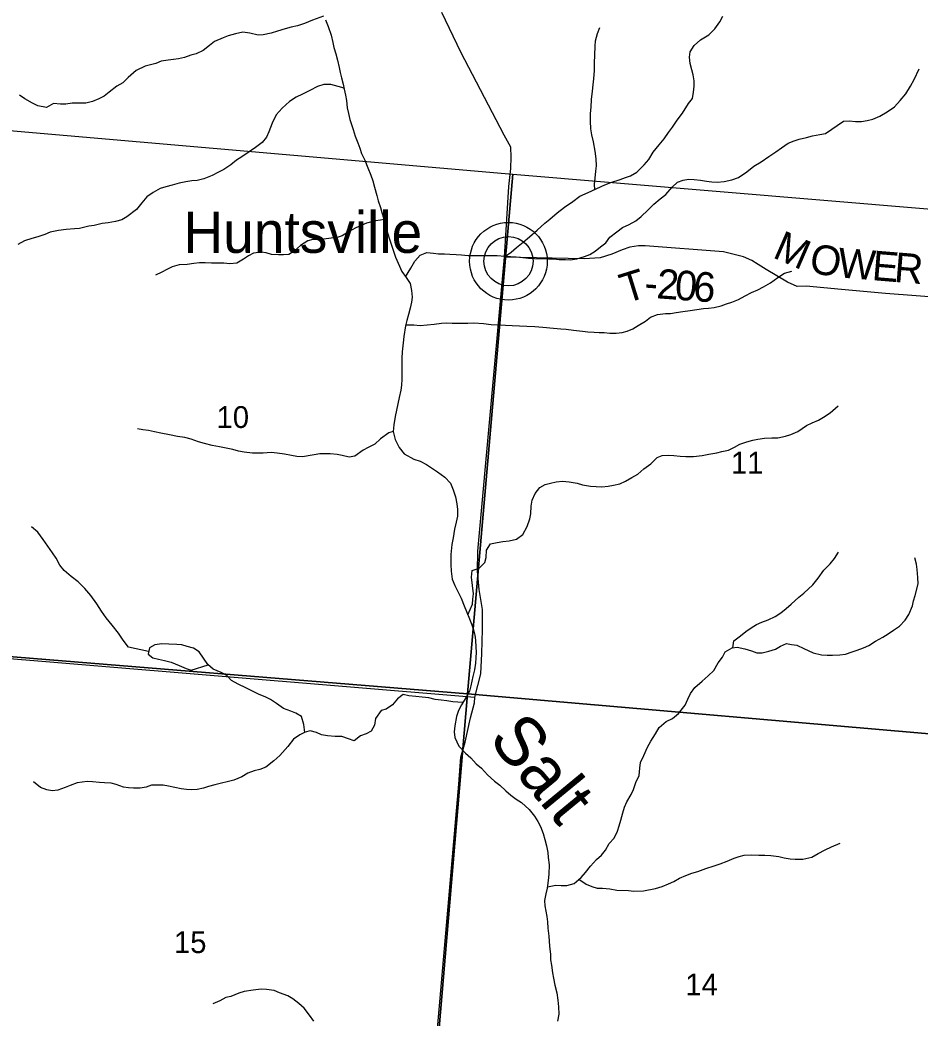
# Model space of a CAD drawing. Extents: x 1643459 to 2064572, y 425441 to 780708.
# Drawn here: x 1887412 to 1896522, y 553249 to 563347 of the extents above; entities that cross this region are included whole.
import ezdxf

# ---------------------------------------------------------------- set-up
doc = ezdxf.new("R2010")
doc.units = 0
for name, color, linetype in [('GE_P_Alignment_100_Curve_Data', 7, 'Continuous'), ('GM_X_Adjacent_County', 7, 'Continuous'), ('GM_X_Major_River', 7, 'Continuous'), ('GM_X_Major_River_Text', 7, 'Continuous'), ('GM_X_Minor_Lake', 7, 'Continuous'), ('GM_X_Rail_Line', 7, 'Continuous'), ('GM_X_State_Route', 7, 'Continuous'), ('GM_X_State_Shield', 7, 'Continuous'), ('GM_X_Township_ROW', 7, 'Continuous'), ('GM_X_Unincorporated_Text', 7, 'Continuous'), ('GM_X_US_Route', 7, 'Continuous')]:
    doc.layers.add(name, color=color, linetype=linetype)

msp = doc.modelspace()

# ---------------------------------------------------------------- linework, layer by layer
at = {"layer": 'GE_P_Alignment_100_Curve_Data'}
for radius in [393, 249]:
    msp.add_circle((1892356, 560906), radius, dxfattribs=at)
at = {"layer": 'GM_X_Major_River_Text'}
for points in [[(1894885, 560872), (1894819, 560915), (1894736, 560952), (1894532, 561003), (1893739, 561062), (1893673, 561061), (1893585, 561050), (1893508, 561021), (1893404, 560978), (1893283, 560939), (1893123, 560929), (1892315, 560949)], [(1897503, 560477), (1896172, 560579), (1895728, 560619), (1895368, 560653), (1895278, 560652), (1895179, 560696), (1894966, 560821), (1894885, 560872)], [(1876241, 557816), (1881411, 557404), (1886775, 556930), (1892015, 556496)]]:
    msp.add_lwpolyline(points, dxfattribs=at)
at = {"layer": 'GM_X_Minor_Lake'}
msp.add_lwpolyline([(1891467, 551170), (1891853, 555616), (1891875, 555889), (1891917, 556041), (1891972, 556288), (1892012, 556438), (1892015, 556496), (1892078, 556732), (1892086, 556937), (1892095, 557179), (1892092, 557384), (1892058, 557585), (1892043, 557770), (1892047, 557973), (1892315, 560949), (1892360, 561661), (1892381, 561844), (1892382, 561960), (1892381, 562062), (1892313, 562182), (1891875, 563022), (1891682, 563424)], dxfattribs=at)
at = {"layer": 'GM_X_Rail_Line'}
msp.add_line((1892356, 560906), (1892356, 560906), dxfattribs=at)
at = {"layer": 'GM_X_State_Route'}
for points in [[(1892399, 561787), (1891943, 556530), (1886800, 556947), (1887147, 562241)], [(1897606, 561351), (1897162, 556078), (1891943, 556530), (1892399, 561787)], [(1886800, 556947), (1891943, 556530), (1891491, 551199), (1886336, 551627)], [(1891943, 556530), (1897162, 556078), (1896690, 550827), (1891491, 551199)]]:
    msp.add_lwpolyline(points, close=True, dxfattribs=at)
at = {"layer": 'GM_X_Unincorporated_Text'}
for points in [[(1890503, 563347), (1890533, 563281), (1890562, 563193), (1890580, 563120), (1890590, 563070), (1890608, 563004), (1890626, 562941), (1890642, 562865), (1890654, 562815), (1890668, 562761), (1890682, 562698), (1890694, 562646), (1890708, 562586), (1890716, 562532), (1890724, 562457), (1890736, 562401), (1890752, 562341), (1890784, 562240), (1890804, 562172), (1890832, 562103), (1890852, 562051), (1890868, 561995), (1890902, 561928), (1890934, 561850), (1890962, 561778), (1890983, 561719), (1890999, 561657), (1891023, 561570), (1891039, 561516), (1891061, 561450), (1891075, 561398), (1891093, 561345), (1891113, 561271), (1891131, 561195), (1891157, 561118), (1891213, 560949), (1891239, 560887), (1891277, 560802)], [(1891277, 560802), (1891320, 560742), (1891360, 560681), (1891376, 560611), (1891382, 560541), (1891376, 560491), (1891361, 560433), (1891345, 560367), (1891327, 560307), (1891315, 560253), (1891298, 560144), (1891290, 560080), (1891280, 559990), (1891278, 559926), (1891277, 559713), (1891273, 559651), (1891267, 559601), (1891250, 559529), (1891224, 559399), (1891210, 559335), (1891197, 559252), (1891189, 559182), (1891211, 559102), (1891249, 559023), (1891300, 558959), (1891397, 558902), (1891463, 558883), (1891528, 558851), (1891586, 558810), (1891639, 558774), (1891713, 558721), (1891770, 558661), (1891798, 558594), (1891820, 558522), (1891832, 558452), (1891842, 558395), (1891840, 558327), (1891827, 558267), (1891809, 558197), (1891795, 558107), (1891782, 558039), (1891772, 557940), (1891774, 557838), (1891776, 557772), (1891786, 557688), (1891814, 557627), (1891848, 557559), (1891876, 557496), (1891908, 557420), (1891930, 557362), (1891961, 557289), (1891985, 557227), (1892001, 557177), (1892017, 557122), (1892023, 557072), (1892027, 557002), (1892029, 556952), (1892026, 556892), (1892022, 556841), (1892012, 556773), (1891996, 556703), (1891975, 556609), (1891963, 556555), (1891929, 556497), (1891882, 556419), (1891852, 556359), (1891831, 556299), (1891813, 556205), (1891807, 556145), (1891815, 556089), (1891853, 556000), (1891921, 555928), (1891974, 555881), (1892028, 555820), (1892083, 555776), (1892145, 555711), (1892214, 555647), (1892270, 555604), (1892328, 555548), (1892379, 555505), (1892433, 555464), (1892488, 555430), (1892566, 555359), (1892619, 555293), (1892653, 555238), (1892681, 555186), (1892709, 555117), (1892725, 555057), (1892741, 554991), (1892755, 554923), (1892759, 554872), (1892769, 554800), (1892765, 554706), (1892759, 554640), (1892748, 554564), (1892736, 554506), (1892722, 554439), (1892724, 554383), (1892744, 554275), (1892750, 554221), (1892756, 554160)], [(1892756, 554160), (1892764, 554078), (1892767, 554026), (1892773, 553976), (1892781, 553893), (1892783, 553839), (1892791, 553783), (1892803, 553705), (1892813, 553652), (1892827, 553582), (1892845, 553504), (1892857, 553430), (1892863, 553361), (1892865, 553289), (1892851, 553219)]]:
    msp.add_lwpolyline(points, dxfattribs=at)
at = {"layer": 'GM_X_US_Route'}
for points in [[(1892323, 560959), (1892326, 560959), (1892385, 560999), (1892437, 561045), (1892504, 561100), (1892569, 561154), (1892648, 561222), (1892725, 561293), (1892775, 561333), (1892850, 561395), (1892923, 561452), (1893006, 561512), (1893077, 561564), (1893131, 561587), (1893200, 561617), (1893251, 561641), (1893333, 561680), (1893392, 561704), (1893487, 561733), (1893540, 561753), (1893590, 561770), (1893657, 561808), (1893728, 561882), (1893778, 561934), (1893821, 562009), (1893880, 562083), (1893932, 562145), (1893975, 562209), (1894015, 562263), (1894062, 562333), (1894117, 562406), (1894179, 562502), (1894218, 562554), (1894230, 562616), (1894236, 562678), (1894234, 562731), (1894225, 562793), (1894213, 562843), (1894196, 562907), (1894187, 562972), (1894195, 563026), (1894237, 563088), (1894300, 563145), (1894385, 563197), (1894446, 563259), (1894496, 563330), (1894525, 563386)], [(1890484, 563385), (1890374, 563344), (1890293, 563313), (1890220, 563287), (1890158, 563274), (1890095, 563256), (1890020, 563233), (1889956, 563213), (1889875, 563196), (1889822, 563192), (1889738, 563213), (1889669, 563223), (1889592, 563208), (1889521, 563186), (1889469, 563168), (1889382, 563131), (1889329, 563089), (1889265, 563040), (1889196, 563006), (1889141, 562990), (1889077, 562969), (1889018, 562955), (1888967, 562947), (1888913, 562940), (1888842, 562930), (1888786, 562907), (1888678, 562881), (1888587, 562836), (1888507, 562764), (1888452, 562712), (1888391, 562677), (1888316, 562617), (1888264, 562575), (1888209, 562550), (1888146, 562522), (1888078, 562505), (1888011, 562505), (1887942, 562504), (1887876, 562496), (1887823, 562496), (1887751, 562501), (1887682, 562461), (1887593, 562480), (1887538, 562506), (1887460, 562551), (1887409, 562588)], [(1893229, 561630), (1893228, 561685), (1893235, 561745), (1893241, 561819), (1893247, 561873), (1893245, 561943), (1893235, 562020), (1893217, 562114), (1893199, 562186), (1893189, 562245), (1893185, 562325), (1893188, 562401), (1893192, 562465), (1893198, 562544), (1893206, 562626), (1893214, 562690), (1893221, 562752), (1893227, 562836), (1893227, 562912), (1893229, 562991), (1893233, 563083), (1893238, 563135), (1893256, 563211), (1893280, 563271)], [(1895566, 562197), (1895748, 562322), (1895803, 562328), (1895870, 562321), (1895928, 562321), (1895985, 562329), (1896043, 562344), (1896114, 562374), (1896189, 562419), (1896262, 562469), (1896320, 562533), (1896379, 562601), (1896424, 562679), (1896462, 562746), (1896513, 562854)], [(1890693, 562649), (1890692, 562658), (1890631, 562673), (1890558, 562695), (1890488, 562694), (1890423, 562674), (1890346, 562634), (1890273, 562597), (1890209, 562565), (1890140, 562522), (1890067, 562456), (1890006, 562388), (1889964, 562304), (1889931, 562216), (1889907, 562160), (1889862, 562106), (1889796, 562057), (1889731, 562013), (1889656, 561964), (1889603, 561930), (1889545, 561882), (1889476, 561836), (1889423, 561807), (1889357, 561775), (1889272, 561740), (1889207, 561722), (1889153, 561718), (1889092, 561711), (1889025, 561695), (1888951, 561676), (1888890, 561660), (1888831, 561641), (1888759, 561601), (1888696, 561557), (1888645, 561496), (1888593, 561430), (1888495, 561354), (1888443, 561326), (1888378, 561307), (1888305, 561295), (1888245, 561288), (1888162, 561268), (1888109, 561261), (1888014, 561239), (1887964, 561234), (1887879, 561226), (1887802, 561217), (1887719, 561199), (1887663, 561178), (1887594, 561154), (1887532, 561135), (1887457, 561111), (1887390, 561075)], [(1891314, 560750), (1891368, 560836), (1891407, 560906), (1891462, 560966), (1891530, 560993), (1891599, 560987), (1891649, 560980), (1891710, 560980), (1891763, 560977), (1891827, 560975), (1891880, 560971), (1891948, 560964), (1892055, 560963), (1892118, 560963), (1892175, 560964), (1892243, 560964), (1892318, 560959), (1892377, 560955), (1892433, 560950), (1892500, 560944), (1892560, 560937), (1892619, 560933), (1892762, 560932), (1892815, 560930), (1892869, 560925), (1892932, 560923), (1892982, 560922), (1893049, 560932), (1893126, 560953), (1893180, 560975), (1893233, 561009), (1893286, 561053), (1893342, 561094), (1893381, 561150), (1893452, 561204), (1893510, 561249), (1893579, 561279), (1893644, 561315), (1893700, 561360), (1893767, 561424), (1893828, 561484), (1893893, 561536), (1893949, 561581), (1894014, 561657), (1894067, 561705), (1894125, 561726), (1894178, 561736), (1894234, 561734), (1894299, 561725), (1894362, 561715), (1894414, 561708), (1894469, 561706), (1894539, 561713), (1894616, 561731), (1894685, 561752), (1894770, 561812), (1894841, 561868), (1894915, 561913), (1894992, 561967), (1895063, 562014), (1895120, 562052), (1895188, 562102), (1895249, 562125), (1895300, 562141), (1895372, 562159), (1895435, 562174), (1895506, 562190), (1895566, 562197)], [(1891097, 561330), (1891062, 561323), (1891010, 561316), (1890921, 561290), (1890864, 561269), (1890812, 561243), (1890737, 561203), (1890674, 561164), (1890624, 561148), (1890563, 561139), (1890488, 561129), (1890438, 561125), (1890377, 561126), (1890327, 561114), (1890252, 561067), (1890191, 561013), (1890135, 560975), (1890080, 560970), (1890030, 560972), (1889959, 560976), (1889904, 560991), (1889854, 560999), (1889775, 560988), (1889725, 560960), (1889674, 560928), (1889607, 560885), (1889535, 560879), (1889474, 560886), (1889407, 560888), (1889351, 560885), (1889286, 560891), (1889228, 560890), (1889173, 560882), (1889104, 560874), (1889024, 560869), (1888951, 560849), (1888900, 560822), (1888848, 560796), (1888785, 560766)], [(1891317, 560264), (1891397, 560264), (1891462, 560257), (1891533, 560263), (1891603, 560270), (1891680, 560280), (1891731, 560282), (1891785, 560281), (1891860, 560279), (1891945, 560280), (1892007, 560282), (1892104, 560277), (1892181, 560266), (1892258, 560262), (1892325, 560259), (1892395, 560257), (1892468, 560252), (1892541, 560250), (1892623, 560245), (1892704, 560238), (1892811, 560230), (1892886, 560223), (1892940, 560219), (1893013, 560208), (1893106, 560197), (1893161, 560193), (1893223, 560188), (1893274, 560186), (1893326, 560184), (1893383, 560179), (1893445, 560179), (1893506, 560184), (1893558, 560198), (1893615, 560222), (1893670, 560255), (1893742, 560301), (1893795, 560341), (1893864, 560366), (1893947, 560376), (1893997, 560379), (1894052, 560387), (1894122, 560397), (1894195, 560408), (1894264, 560418), (1894330, 560427), (1894381, 560431), (1894438, 560438), (1894510, 560454), (1894563, 560474), (1894617, 560491), (1894686, 560519), (1894751, 560556), (1894816, 560590), (1894880, 560618), (1894939, 560647), (1895008, 560689), (1895081, 560741), (1895149, 560786), (1895224, 560806)], [(1891945, 557327), (1891993, 557435), (1891997, 557486), (1892002, 557542), (1891992, 557624), (1891982, 557708), (1891990, 557778), (1892059, 557800), (1892117, 557858), (1892132, 557910), (1892134, 557984), (1892176, 558046), (1892241, 558061), (1892300, 558071), (1892362, 558077), (1892437, 558094), (1892502, 558142), (1892546, 558222), (1892573, 558300), (1892581, 558352), (1892587, 558428), (1892595, 558490), (1892628, 558556), (1892672, 558618), (1892729, 558648), (1892780, 558661), (1892840, 558675), (1892903, 558682), (1892969, 558674), (1893052, 558661), (1893107, 558645), (1893185, 558632), (1893244, 558626), (1893301, 558623), (1893365, 558631), (1893420, 558639), (1893482, 558654), (1893541, 558682), (1893604, 558717), (1893664, 558753), (1893727, 558807), (1893796, 558858), (1893861, 558920), (1893913, 558942), (1893976, 558943), (1894030, 558941), (1894093, 558935), (1894150, 558930), (1894230, 558932), (1894317, 558941), (1894384, 558954), (1894465, 558966), (1894517, 558980), (1894582, 558995), (1894645, 559025), (1894697, 559054), (1894768, 559080), (1894829, 559096), (1894879, 559107), (1894948, 559117), (1895022, 559118), (1895083, 559120), (1895160, 559135), (1895214, 559153), (1895285, 559185), (1895372, 559244), (1895429, 559270), (1895493, 559299), (1895544, 559327), (1895611, 559373), (1895694, 559444)], [(1891189, 559182), (1891147, 559169), (1891062, 559109), (1891003, 559057), (1890936, 559020), (1890886, 558996), (1890803, 558934), (1890744, 558925), (1890672, 558941), (1890621, 558950), (1890552, 558958), (1890447, 558957), (1890391, 558949), (1890328, 558938), (1890276, 558926), (1890213, 558931), (1890161, 558939), (1890088, 558954), (1890015, 558964), (1889955, 558971), (1889872, 558965), (1889815, 558964), (1889765, 558964), (1889682, 558973), (1889625, 558983), (1889567, 559000), (1889500, 559014), (1889430, 559027), (1889359, 559041), (1889280, 559062), (1889220, 559080), (1889145, 559107), (1889080, 559123), (1889008, 559134), (1888927, 559151), (1888838, 559167), (1888773, 559180), (1888713, 559192), (1888654, 559201), (1888602, 559211)], [(1888714, 556958), (1888512, 557003), (1888456, 557072), (1888408, 557143), (1888345, 557225), (1888283, 557298), (1888236, 557364), (1888190, 557441), (1888130, 557524), (1888069, 557594), (1888001, 557661), (1887930, 557716), (1887858, 557776), (1887817, 557831), (1887777, 557903), (1887741, 557956), (1887694, 558022), (1887648, 558091), (1887594, 558165), (1887529, 558218)], [(1894626, 556996), (1894636, 557065), (1894703, 557117), (1894760, 557159), (1894812, 557198), (1894865, 557230), (1894921, 557254), (1894986, 557279), (1895055, 557311), (1895112, 557349), (1895166, 557392), (1895219, 557436), (1895294, 557508), (1895346, 557549), (1895437, 557633), (1895490, 557699), (1895547, 557779), (1895611, 557844), (1895656, 557898), (1895697, 557962)], [(1892750, 554575), (1892837, 554593), (1892888, 554591), (1892948, 554590), (1893021, 554610), (1893092, 554671), (1893135, 554723), (1893185, 554785), (1893246, 554853), (1893297, 554897), (1893337, 554948), (1893376, 555016), (1893426, 555070), (1893461, 555140), (1893477, 555194), (1893493, 555252), (1893514, 555326), (1893530, 555382), (1893554, 555436), (1893597, 555510), (1893621, 555562), (1893644, 555632), (1893678, 555702), (1893686, 555778), (1893692, 555836), (1893725, 555904), (1893765, 555990), (1893798, 556050), (1893843, 556126), (1893883, 556190), (1893952, 556248), (1894015, 556281), (1894077, 556329), (1894144, 556415), (1894170, 556475), (1894197, 556533), (1894243, 556595), (1894318, 556658), (1894377, 556710), (1894436, 556764), (1894478, 556844), (1894521, 556900), (1894549, 556953), (1894620, 556995), (1894670, 557003), (1894747, 556986), (1894816, 556966), (1894870, 556945), (1894923, 556945), (1894992, 556962), (1895058, 556982), (1895111, 557012), (1895171, 557037), (1895222, 557029), (1895274, 557022), (1895345, 556988), (1895440, 556943), (1895523, 556924), (1895581, 556922), (1895636, 556921), (1895710, 556923), (1895767, 556931), (1895834, 556954), (1895884, 556972), (1895949, 556995), (1896002, 557017), (1896072, 557061), (1896145, 557102), (1896198, 557138), (1896254, 557174), (1896313, 557215), (1896370, 557273), (1896408, 557333), (1896445, 557419), (1896457, 557469), (1896471, 557523), (1896502, 557643), (1896500, 557707), (1896492, 557786), (1896486, 557842), (1896470, 557904)], [(1889314, 556825), (1889225, 556954), (1889167, 556991), (1889104, 557009), (1889050, 557024), (1888999, 557030), (1888918, 557033), (1888848, 557035), (1888777, 557026), (1888722, 556996), (1888708, 556932), (1888758, 556895), (1888815, 556879), (1888874, 556868), (1888944, 556848), (1889025, 556815), (1889093, 556787), (1889144, 556770), (1889316, 556823)], [(1890296, 556139), (1890284, 556220), (1890260, 556301), (1890203, 556333), (1890153, 556354), (1890080, 556382), (1890008, 556433), (1889949, 556473), (1889893, 556500), (1889834, 556522), (1889780, 556551), (1889699, 556590), (1889620, 556628), (1889552, 556663), (1889507, 556715), (1889447, 556746), (1889366, 556779), (1889312, 556827)], [(1891895, 556441), (1891793, 556448), (1891733, 556458), (1891674, 556465), (1891613, 556473), (1891551, 556488), (1891482, 556496), (1891420, 556503), (1891347, 556509), (1891290, 556522), (1891234, 556478), (1891181, 556418), (1891118, 556373), (1891068, 556361), (1891009, 556279), (1891001, 556213), (1890966, 556151), (1890916, 556123), (1890859, 556104), (1890793, 556054), (1890738, 556075), (1890669, 556097), (1890601, 556096), (1890524, 556104), (1890465, 556115), (1890415, 556139), (1890348, 556154), (1890298, 556140), (1890245, 556116), (1890181, 556069), (1890122, 555997), (1890041, 555907), (1889982, 555851), (1889901, 555788), (1889839, 555764), (1889782, 555751), (1889719, 555727), (1889659, 555689), (1889576, 555656), (1889509, 555640), (1889451, 555627), (1889384, 555609), (1889321, 555591), (1889271, 555574), (1889204, 555560), (1889151, 555559), (1889097, 555561), (1889042, 555567), (1888978, 555582), (1888915, 555594), (1888861, 555605), (1888806, 555605), (1888744, 555604), (1888691, 555584), (1888630, 555576), (1888560, 555575), (1888509, 555579), (1888459, 555586), (1888386, 555612), (1888334, 555627), (1888267, 555629), (1888216, 555632), (1888146, 555638), (1888091, 555643), (1887992, 555629), (1887921, 555602), (1887869, 555580), (1887796, 555554), (1887738, 555547), (1887683, 555557), (1887621, 555582), (1887550, 555638)], [(1893070, 554652), (1893068, 554654), (1893142, 554603), (1893199, 554580), (1893255, 554564), (1893308, 554562), (1893381, 554557), (1893453, 554544), (1893570, 554538), (1893625, 554533), (1893722, 554536), (1893843, 554560), (1893912, 554579), (1893975, 554607), (1894031, 554632), (1894086, 554664), (1894150, 554692), (1894211, 554715), (1894274, 554733), (1894353, 554763), (1894439, 554788), (1894500, 554810), (1894569, 554835), (1894640, 554865), (1894692, 554884), (1894743, 554896), (1894821, 554900), (1894890, 554897), (1894951, 554897), (1895011, 554894), (1895094, 554883), (1895145, 554871), (1895207, 554861), (1895258, 554858), (1895336, 554856), (1895427, 554877), (1895492, 554913), (1895561, 554952), (1895625, 554982), (1895712, 555019)], [(1890386, 553217), (1890344, 553277), (1890288, 553350), (1890233, 553396), (1890175, 553445), (1890124, 553475), (1890038, 553504), (1889985, 553527), (1889906, 553539), (1889852, 553540), (1889773, 553532), (1889682, 553519), (1889626, 553499), (1889547, 553468), (1889496, 553456), (1889436, 553424), (1889363, 553393)]]:
    msp.add_lwpolyline(points, dxfattribs=at)

# ---------------------------------------------------------------- texts
at = {"layer": 'GM_X_Adjacent_County'}
for s, p in [('10', (1889402, 559219)), ('11', (1894608, 558757)), ('15', (1888971, 553906)), ('14', (1894146, 553478))]:
    msp.add_text(s, height=221, rotation=0, dxfattribs=at).set_placement(p)
at = {"layer": 'GM_X_Major_River'}
for s, rotation, p in [('M', 336.4731, (1895019, 560948)), ('O', 349.648, (1895389, 560796)), ('W', 355.409, (1895682, 560744)), ('E', 355.3018, (1896028, 560716)), ('R', 355.3015, (1896252, 560698)), ('T', 17.2674, (1893541, 560477)), ('2', 355.8017, (1893849, 560532)), ('0', 355.7783, (1894033, 560518)), ('6', 355.7783, (1894218, 560505)), ('-', 355.8983, (1893726, 560541))]:
    msp.add_text(s, height=300, rotation=rotation, dxfattribs=at).set_placement(p)
at = {"layer": 'GM_X_State_Shield'}
msp.add_text('Salt', height=500, rotation=309.4485, dxfattribs=at).set_placement((1892143, 556066))
at = {"layer": 'GM_X_Township_ROW'}
msp.add_text('Huntsville', height=417, rotation=0, dxfattribs=at).set_placement((1889066, 560991))

doc.saveas('drawing.dxf')
